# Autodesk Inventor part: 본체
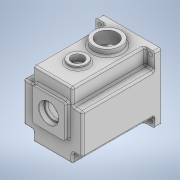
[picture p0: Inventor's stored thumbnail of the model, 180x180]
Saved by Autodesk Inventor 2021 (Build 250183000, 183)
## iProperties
Created: 2022-08
Part Number: 본체
Material: 일반
Document SubType Name: Modeling
Designer: Owner
Density: 1 g/cm^3
Appearance: 기본값
Author: Owner
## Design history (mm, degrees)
sketch "스케치1"
  geometry: L1 (-49, 55)-(49, 55); L2 (49, 55)-(49, -55); L3 (49, -55)-(-49, -55); L4 (-49, -55)-(-49, 55); L5 (-49, 55)-(49, -55); L6 (49, 55)-(-49, -55); 1 further point
  constraints: 12 end point, 2 midpoint, 2 parallel, 1 horizontal, 1 perpendicular
  dimensions: "d0" = 98 distance of L2.end L3.end; "d1" = 110 distance of L1.end L2.end
extrude "돌출1" new body sketch "스케치1" distance "d2" = 130; taper "d3" = 0 deg
sketch "스케치3"
  geometry: L1 (-49, -55)-(49, -55) reference; L2 (49, -55)-(49, 55) reference; L3 (49, 55)-(-49, 55) reference; L4 (-49, 55)-(49, 55) reference; L5 (33, 55)-(33, 28); L6 (33, 28)-(49, 28); L7 (49, 55)-(49, -55) reference; L8 (33, 55)-(49, 55); L9 (49, 55)-(49, 28); L10 (33, -38)-(33, -55); L11 (49, -55)-(-49, -55) reference; L12 (49, -55)-(49, -38); L13 (33, -38)-(49, -38); L14 (33, -55)-(49, -55); 4 further points
  constraints: 16 end point, 4 perpendicular, 4 point on line, 2 collinear, 1 vertical
  dimensions: "d8" = 16 distance between parallel lines of L2 L5; "d9" = 27 distance between parallel lines of L4 L6; "d12" = 17 distance between parallel lines of L1 L13; "d13" = 16 distance between parallel lines of L2 L10
extrude "돌출3" cut sketch "스케치3" distance "d14" = 120; taper "d15" = 0 deg
sketch "스케치5"
  geometry: L1 (-49, -55)-(49, -55) reference; L2 (-23, 45)-(23, 45); L3 (23, 45)-(23, 30.143); L4 (-23, 30.143)-(-23, 45); L5 (0, 0)-(0, 11.772); A1 r 42 centre (0, -5) between (-23, 30.143) and (23, 30.143)
  constraints: 8 end point, 2 point on circle, 1 centre point, 1 horizontal, 1 parallel, 1 perpendicular, 1 vertical, 1 vertical alignment, 1 other
  dimensions: "d20" = 50 distance from line of L1 A1.centre; "d21" = 46 distance between parallel lines of L3 L4; "d22" = 50 distance from line of A1.centre L2; "d23" = 42 radius of A1
extrude "돌출5" cut sketch "스케치5" distance "d24" = 121; taper "d25" = 0 deg
fillet "모깎기1" dims "d26" = 6
sketch "스케치6"
  geometry: L1 (-23, 33.249)-(-23, 45) reference; L2 (-23, 45)-(23, 45) reference; L3 (23, 45)-(23, 33.249) reference; L4 (26, 33.249)-(26, 48); L5 (26, 48)-(-26, 48); L6 (-26, 48)-(-26, 33.249); A1 r 6 centre (-29, 33.249) between (-25.375, 28.468) and (-23, 33.249) reference; A2 r 6 centre (29, 33.249) between (23, 33.249) and (25.375, 28.468) reference; A3 r 42 centre (0, -5) between (-25.375, 28.468) and (25.375, 28.468) reference; A4 r 3 centre (29, 33.249) between (26, 33.249) and (27.188, 30.859); A5 r 3 centre (-29, 33.249) between (-27.188, 30.859) and (-26, 33.249); A6 r 45 centre (0, -5) between (-27.188, 30.859) and (27.188, 30.859); 1 further point
  constraints: 6 end point, 6 point on circle, 3 centre point, 5 other
  dimensions: "d27" = 3 radial gap between concentric circles of A3 A6
extrude "돌출6" cut sketch "스케치6" distance "d28" = 9; taper "d29" = 0 deg
sketch "스케치7"
  geometry: A1 r 42 centre (0, -5) between (-25.375, 28.468) and (25.375, 28.468) reference; A2 r 15 centre (0, -25) between (-8.978, -12.984) and (8.978, -12.984); A3 r 21 centre (0, 6) between (8.978, -12.984) and (-8.978, -12.984); 1 further point
  constraints: 4 point on circle, 2 centre point, 2 vertical alignment
  dimensions: "d30" = 30 diameter of A2; "d31" = 42 diameter of A3; "d32" = 20 distance of A2.centre A1.centre; "d33" = 11 distance of A3.centre A1.centre
extrude "돌출7" join sketch "스케치7" distance "d34" = 7; taper "d35" = 0 deg
sketch "스케치8"
  geometry: A1 r 15 centre (0, -25) between (-8.978, -12.984) and (8.978, -12.984) reference; 2 further points
  constraints: 1 coincident
hole "구멍1" sketch "스케치8" at (0, -25) diameter "d36" = 19; stored, may be unused: countersink angle "d40" = 90 deg, drill point angle "d42" = 0 deg; dims "d37" = 12, "d38" = 22, "d39" = 7, "d41" = 10
sketch "스케치16"
  geometry: L1 (-33, -55)-(33, -55) reference; L2 (-27, 33)-(27, 33); L3 (27, 33)-(27, -21); L4 (27, -21)-(-27, -21); L5 (-27, -21)-(-27, 33); L6 (-27, 33)-(27, -21); L7 (27, 33)-(-27, -21); 3 further points
  constraints: 12 end point, 3 midpoint, 2 parallel, 1 horizontal, 1 perpendicular, 1 vertical alignment
  dimensions: "d79" = 54 distance of L2.start L2.end; "d80" = 54 distance of L2.end L3.end; "d81" = 61 distance from line of point (0, 6) L1
extrude "돌출13" join sketch "스케치16" distance "d82" = 7; taper "d83" = 0 deg
sketch "스케치17"
  geometry: A1 r 21 centre (0, 6) between (8.978, -12.984) and (-8.978, -12.984) reference; 2 further points
  constraints: 1 coincident
hole "구멍4" sketch "스케치17" at (0, 6) diameter "d84" = 28; stored, may be unused: countersink angle "d88" = 90 deg, drill point angle "d90" = 0 deg; dims "d85" = 12, "d86" = 35, "d87" = 10, "d89" = 10
sketch "스케치18"
  geometry: C1 r 14 at (0, 6) reference; C2 r 16 at (0, 6); 1 further point
  constraints: 1 centre point, 1 coincident
  dimensions: "d91" = 32 diameter of C2
extrude "돌출14" cut sketch "스케치18" distance "d92" = 8.3; taper "d93" = 0 deg
sketch "스케치21"
  geometry: L1 (36, -1)-(41.809, -1); L2 (36, -9)-(41.809, -9); A1 r 45 centre (0, -5) between (-27.188, 30.859) and (27.188, 30.859) reference; A2 r 42 centre (0, -5) between (-25.375, 28.468) and (25.375, 28.468) reference; A3 r 4 centre (36, -5) between (36, -1) and (36, -9); A4 r 42 centre (0, -5) between (-25.375, 28.468) and (25.375, 28.468) reference; 3 further points
  constraints: 4 end point, 4 point on circle, 2 horizontal, 2 tangent, 1 centre point, 1 horizontal alignment
  dimensions: "d101" = 8 diameter of A3; "d102" = 36 distance of A3.centre A1.centre
extrude "돌출16" join sketch "스케치21" distance "d103" = 121; taper "d104" = 0 deg
sketch "스케치22"
  geometry: L1 (82, -130)-(16, -130) reference; L2 (0, 0)-(98, 0) reference; C1 r 15 at (49, -89); 2 further points
  constraints: 1 centre point, 1 midpoint, 1 vertical alignment
  dimensions: "d105" = 30 diameter of C1; "d106" = 89 distance from line of C1.centre L2
extrude "돌출17" join sketch "스케치22" distance "d107" = 5; taper "d108" = 0 deg
sketch "스케치23"
  geometry: L1 (82, -130)-(16, -130) reference; L2 (0, 0)-(98, 0) reference; C1 r 22.5 at (49, -40); 2 further points
  constraints: 1 centre point, 1 midpoint, 1 vertical alignment
  dimensions: "d109" = 40 distance from line of C1.centre L2; "d110" = 45 diameter of C1
extrude "돌출18" join sketch "스케치23" distance "d111" = 10; taper "d112" = 0 deg
sketch "스케치25"
  geometry: C1 r 15 at (23, -32) reference; 2 further points
  constraints: 1 coincident
hole "구멍5" sketch "스케치25" at (23, -32) diameter "d113" = 20; stored, may be unused: countersink angle "d117" = 90 deg, drill point angle "d119" = 0 deg; dims "d114" = 12, "d115" = 30, "d116" = 5, "d118" = 10
sketch "스케치26"
  geometry: C1 r 22.5 at (0, 0) reference; 2 further points
  constraints: 1 coincident
hole "구멍6" sketch "스케치26" at (0, 0) diameter "d120" = 33.376; stored, may be unused: countersink angle "d124" = 90 deg, drill point angle "d126" = 0 deg; dims "d121" = 70, "d122" = 30, "d123" = 5, "d125" = 52.05
sketch "스케치27"
  geometry: A1 r 4 centre (36, -5) between (36, -1) and (36, -9) reference; 2 further points
  constraints: 1 coincident
hole "구멍7" sketch "스케치27" at (36, -5) diameter "d127" = 3.242; stored, may be unused: countersink angle "d131" = 90 deg, drill point angle "d133" = 118 deg; dims "d128" = 7, "d129" = 30, "d130" = 5, "d132" = 9
fillet "모깎기2" dims "d134" = 3
fillet "모깎기3" dims "d135" = 3
fillet "모깎기4" dims "d136" = 3
fillet "모깎기5" dims "d137" = 3
fillet "모깎기6" dims "d138" = 3
sketch "스케치28"
  geometry: L1 (49, 52)-(49, 30.196) reference; L2 (35.196, 55)-(46, 55) reference; C1 r 3.5 at (42, 48); 1 further point
  constraints: 1 centre point
  dimensions: "d139" = 7 distance from line of L2 C1.centre; "d140" = 7 distance from line of L1 C1.centre; "d141" = 7 diameter of C1
extrude "돌출19" cut sketch "스케치28" extent not by distance; stored distance "d142" = 0; taper "d143" = 0 deg
fillet "모깎기7" dims "d144" = 3
fillet "모깎기8" dims "d148" = 6
fillet "모깎기9" dims "d149" = 3
fillet "모깎기10" dims "d150" = 3
fillet "모깎기11" dims "d151" = 0.3
chamfer "모따기2" distance "d152" = 0.8; stored, may be unused: second distance "d153" = 2, angle "d154" = 30 deg
chamfer "모따기3" distance "d155" = 1; stored, may be unused: second distance "d156" = 2, angle "d157" = 30 deg
node "솔리드1"
mirror "미러1"
mirror "미러2"
mirror "미러3"
mirror "미러4"
mirror "미러5"
feature "A9D066F2-1C7D-4E18-AEED-F7BC21143FA4" dims "d36" = 19, "d37" = 12, "d38" = 22, "d39" = 7, "d40" = 90 deg, "d41" = 10, "d42" = 0
